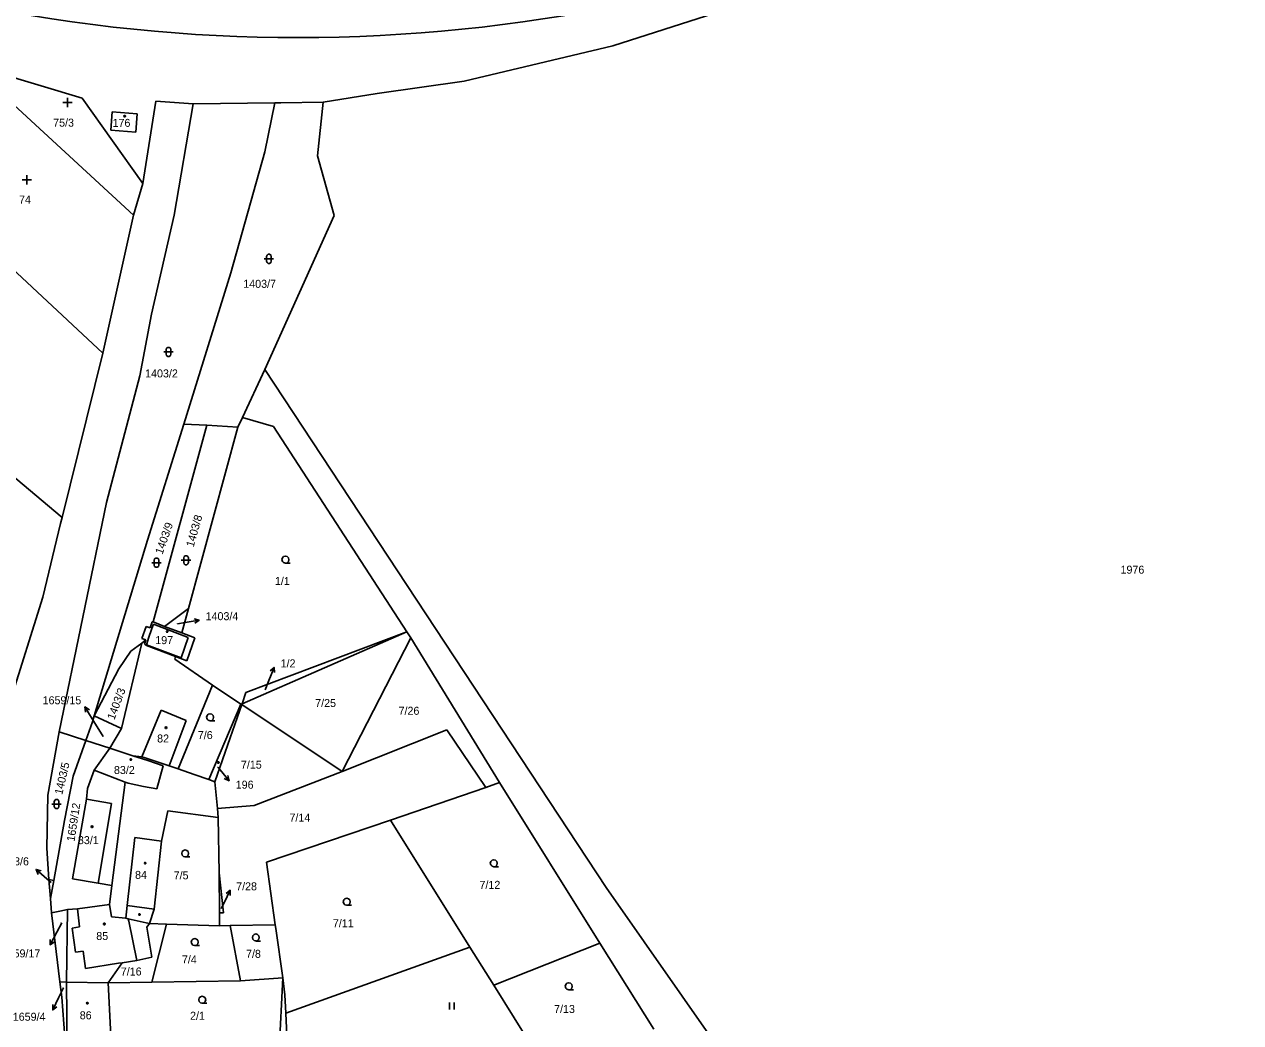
# Model space of a CAD drawing. Extents: x -802857 to -799647, y -1020285 to -1015884.
# Drawn here: x -801490 to -801231.6, y -1017461.1 to -1017248.9 of the extents above; entities that cross this region are included whole.
import ezdxf

# ---------------------------------------------------------------- set-up
doc = ezdxf.new("R2010")
doc.units = 0
for name, color, linetype in [('Default', 7, 'Continuous'), ('KN_HRANICE', 7, 'Continuous'), ('KN_KULTURY', 7, 'Continuous'), ('KN_PARCELY', 7, 'Continuous'), ('KN_SLUCKY', 7, 'Continuous'), ('Železniční svršek', 7, 'Continuous')]:
    doc.layers.add(name, color=color, linetype=linetype)

# ---------------------------------------------------------------- blocks, each defined once
blk = doc.blocks.new('304')
at = {"layer": 'Default'}
blk.add_lwpolyline([(0, 0), (-0.38, 0.1), (-0.65, 0.37), (-0.75, 0.74), (-0.65, 1.11), (-0.38, 1.38), (-0.01, 1.48), (0.36, 1.38), (0.63, 1.11), (0.73, 0.73), (0.63, 0.35), (0.36, 0.08), (-0.02, -0.02), (0.98, -0.02)], dxfattribs=at)
blk = doc.blocks.new('306')
at = {"layer": 'Default'}
for p, q in [((-0.5, 1.5), (-0.5, 0)), ((0.5, 0), (0.5, 1.5))]:
    blk.add_line(p, q, dxfattribs=at)
blk = doc.blocks.new('315')
at = {"layer": 'Default'}
for p, q in [((-1, 1), (1, 1)), ((0, 0), (0, 2))]:
    blk.add_line(p, q, dxfattribs=at)
blk = doc.blocks.new('316')
at = {"layer": 'Default'}
for points in [[(-1, 1), (0.27, 1), (1, 1)], [(-0.5, 1.5), (-0.4, 1.79), (-0.15, 1.97), (0.16, 1.97), (0.41, 1.79), (0.51, 1.5), (0.51, 0.5), (0.41, 0.21), (0.16, 0.03), (-0.15, 0.03), (-0.4, 0.21), (-0.5, 0.5), (-0.5, 1.5)]]:
    blk.add_lwpolyline(points, dxfattribs=at)
blk = doc.blocks.new('NAHRADNI_SYMBOL')
at = {"layer": 'Default'}
blk.add_lwpolyline([(0.09, 0.15), (0.18, 0), (0.09, -0.15), (-0.09, -0.15), (-0.18, 0), (-0.09, 0.15), (0.09, 0.15)], dxfattribs=at)
blk = doc.blocks.new('10292')
at = {"layer": 'Default'}
blk.add_line((0, 3), (0, 0), dxfattribs=at)
blk.add_lwpolyline([(-0.5, 2), (0, 3), (0.5, 2)], dxfattribs=at)
blk = doc.blocks.new('402')
at = {"layer": 'Default'}
blk.add_lwpolyline([(0.09, 0.15), (0.18, 0), (0.09, -0.15), (-0.09, -0.15), (-0.18, 0), (-0.09, 0.15), (0.09, 0.15)], dxfattribs=at)

msp = doc.modelspace()

# ---------------------------------------------------------------- linework, layer by layer
at = {"layer": 'KN_HRANICE'}
for p, q in [((-801619.51, -1017238.39), (-801481.95, -1017353.71)), ((-801318.92, -1017238.69), (-801364.93, -1017253.53)), ((-801364.93, -1017253.53), (-801396.54, -1017260.97)), ((-801477.73, -1017264.63), (-801501.56, -1017257.45)), ((-801466.82, -1017289.45), (-801501.56, -1017257.45)), ((-801396.54, -1017260.97), (-801415.01, -1017263.64)), ((-801415.01, -1017263.64), (-801426.49, -1017265.49)), ((-801477.73, -1017264.63), (-801464.79, -1017282.78)), ((-801464.79, -1017282.78), (-801462.07, -1017265.26)), ((-801454.13, -1017265.82), (-801462.07, -1017265.26)), ((-801454.13, -1017265.82), (-801458.15, -1017289.48)), ((-801454.13, -1017265.82), (-801436.73, -1017265.61)), ((-801438.87, -1017276.02), (-801436.73, -1017265.61)), ((-801436.73, -1017265.61), (-801435.52, -1017265.6)), ((-801435.52, -1017265.6), (-801426.49, -1017265.49)), ((-801426.49, -1017265.49), (-801427.72, -1017276.85)), ((-801471.6, -1017271.43), (-801471.3, -1017267.55)), ((-801471.3, -1017267.55), (-801466, -1017267.95)), ((-801466, -1017267.95), (-801466.29, -1017271.83)), ((-801466.29, -1017271.83), (-801471.6, -1017271.43)), ((-801473.28, -1017318.78), (-801518.94, -1017276.33)), ((-801446.14, -1017301.75), (-801438.87, -1017276.02)), ((-801427.72, -1017276.85), (-801424.14, -1017289.58)), ((-801466.82, -1017289.45), (-801464.79, -1017282.78)), ((-801473.28, -1017318.78), (-801466.82, -1017289.45)), ((-801458.15, -1017289.48), (-801462.97, -1017310.53)), ((-801424.14, -1017289.58), (-801438.92, -1017322.27)), ((-801456.12, -1017333.87), (-801446.14, -1017301.75)), ((-801462.97, -1017310.53), (-801465.45, -1017323.65)), ((-801481.95, -1017353.71), (-801473.28, -1017318.78)), ((-801465.45, -1017323.65), (-801472.56, -1017350.57)), ((-801443.65, -1017332.48), (-801438.92, -1017322.27)), ((-801438.92, -1017322.27), (-801366.39, -1017432.38)), ((-801463.78, -1017358.51), (-801456.12, -1017333.87)), ((-801451.19, -1017334.14), (-801462.64, -1017375.93)), ((-801451.19, -1017334.14), (-801456.12, -1017333.87)), ((-801444.59, -1017334.5), (-801451.19, -1017334.14)), ((-801444.59, -1017334.5), (-801443.65, -1017332.48)), ((-801443.65, -1017332.48), (-801437.03, -1017334.42)), ((-801455.08, -1017373.05), (-801444.59, -1017334.5)), ((-801437.03, -1017334.42), (-801408.69, -1017378.05)), ((-801472.56, -1017350.57), (-801482.61, -1017399.26)), ((-801486.04, -1017370.69), (-801482.28, -1017355.03)), ((-801482.28, -1017355.03), (-801481.95, -1017353.71)), ((-801475.12, -1017395.87), (-801463.78, -1017358.51)), ((-801493.03, -1017393.07), (-801486.04, -1017370.69)), ((-801460.21, -1017376.86), (-801455.08, -1017373.05)), ((-801456.5, -1017378.26), (-801455.08, -1017373.05)), ((-801464.99, -1017379.43), (-801464.11, -1017376.89)), ((-801464.11, -1017376.89), (-801463.26, -1017377.18)), ((-801463.26, -1017377.18), (-801462.81, -1017375.87)), ((-801462.81, -1017375.87), (-801462.64, -1017375.93)), ((-801462.64, -1017375.93), (-801460.21, -1017376.86)), ((-801460.21, -1017376.86), (-801456.5, -1017378.26)), ((-801453.76, -1017379.27), (-801456.5, -1017378.26)), ((-801443.73, -1017393.29), (-801408.69, -1017378.05)), ((-801442.91, -1017390.9), (-801408.69, -1017378.05)), ((-801407.88, -1017379.29), (-801408.69, -1017378.05)), ((-801469.37, -1017398.55), (-801465.04, -1017380.4)), ((-801465.04, -1017380.4), (-801467.33, -1017382.12)), ((-801464.14, -1017379.72), (-801465.04, -1017380.4)), ((-801464.14, -1017379.72), (-801464.99, -1017379.43)), ((-801464.45, -1017380.63), (-801464.14, -1017379.72)), ((-801464.01, -1017380.93), (-801464.45, -1017380.63)), ((-801453.76, -1017379.27), (-801455.47, -1017384.17)), ((-801422.42, -1017407.74), (-801407.88, -1017379.29)), ((-801407.88, -1017379.29), (-801389.06, -1017410.03)), ((-801469.88, -1017385.9), (-801467.33, -1017382.12)), ((-801457.88, -1017383.3), (-801464.01, -1017380.93)), ((-801457.88, -1017383.3), (-801458, -1017383.82)), ((-801455.47, -1017384.17), (-801457.88, -1017383.3)), ((-801475.12, -1017395.87), (-801469.88, -1017385.9)), ((-801450.03, -1017389.33), (-801458, -1017383.82)), ((-801450.03, -1017389.33), (-801457.32, -1017407.16)), ((-801443.97, -1017393.39), (-801450.03, -1017389.33)), ((-801443.73, -1017393.29), (-801442.91, -1017390.9)), ((-801443.97, -1017393.39), (-801450.79, -1017409.43)), ((-801446.23, -1017400.56), (-801443.8, -1017393.5)), ((-801443.97, -1017393.39), (-801443.73, -1017393.29)), ((-801443.8, -1017393.5), (-801443.73, -1017393.29)), ((-801443.8, -1017393.5), (-801422.42, -1017407.74)), ((-801475.51, -1017397.16), (-801475.12, -1017395.87)), ((-801469.37, -1017398.55), (-801475.12, -1017395.87)), ((-801476.91, -1017401.11), (-801475.51, -1017397.16)), ((-801471.82, -1017402.77), (-801469.37, -1017398.55)), ((-801400.24, -1017398.84), (-801422.42, -1017407.74)), ((-801391.91, -1017411.13), (-801400.24, -1017398.84)), ((-801484.97, -1017412.74), (-801482.61, -1017399.26)), ((-801476.91, -1017401.11), (-801482.61, -1017399.26)), ((-801479.6, -1017408.7), (-801476.91, -1017401.11)), ((-801471.82, -1017402.77), (-801476.91, -1017401.11)), ((-801449.49, -1017409.89), (-801446.23, -1017400.56)), ((-801475.18, -1017407.42), (-801471.82, -1017402.77)), ((-801471.82, -1017402.77), (-801466.9, -1017404.38)), ((-801466.9, -1017404.38), (-801463.71, -1017405.36)), ((-801466.9, -1017404.38), (-801464.99, -1017404.58)), ((-801464.3, -1017404.78), (-801464.99, -1017404.58)), ((-801459.24, -1017406.5), (-801464.3, -1017404.78)), ((-801463.71, -1017405.36), (-801460.5, -1017406.5)), ((-801460.5, -1017406.5), (-801461.81, -1017411.42)), ((-801457.32, -1017407.16), (-801459.24, -1017406.5)), ((-801481.43, -1017418.11), (-801479.6, -1017408.7)), ((-801475.18, -1017407.42), (-801476.57, -1017411.34)), ((-801468.57, -1017409.95), (-801475.18, -1017407.42)), ((-801453.89, -1017408.33), (-801457.32, -1017407.16)), ((-801450.79, -1017409.43), (-801453.89, -1017408.33)), ((-801422.42, -1017407.74), (-801441.13, -1017414.93)), ((-801476.57, -1017411.34), (-801476.78, -1017413.57)), ((-801468.57, -1017409.95), (-801471.37, -1017431.95)), ((-801467.94, -1017410.19), (-801468.57, -1017409.95)), ((-801464.69, -1017410.9), (-801467.94, -1017410.19)), ((-801461.81, -1017411.42), (-801464.69, -1017410.9)), ((-801449.49, -1017409.89), (-801450.79, -1017409.43)), ((-801449.49, -1017409.89), (-801448.95, -1017415.59)), ((-801412.18, -1017418.02), (-801391.91, -1017411.13)), ((-801391.91, -1017411.13), (-801389.06, -1017410.03)), ((-801367.72, -1017444.15), (-801389.06, -1017410.03)), ((-801485.18, -1017423.98), (-801484.97, -1017412.74)), ((-801476.78, -1017413.57), (-801479.73, -1017430.52)), ((-801459.51, -1017416.03), (-801460.82, -1017422.5)), ((-801448.78, -1017417.45), (-801459.51, -1017416.03)), ((-801441.13, -1017414.93), (-801448.95, -1017415.59)), ((-801448.95, -1017415.59), (-801448.78, -1017417.45)), ((-801483.75, -1017430.88), (-801481.43, -1017418.11)), ((-801448.78, -1017417.45), (-801448.56, -1017429.24)), ((-801438.55, -1017426.97), (-801412.18, -1017418.02)), ((-801395.3, -1017445.02), (-801412.18, -1017418.02)), ((-801484.77, -1017430.63), (-801485.18, -1017423.98)), ((-801460.82, -1017422.5), (-801462.42, -1017436.96)), ((-801438.55, -1017426.97), (-801436.67, -1017440.26)), ((-801448.56, -1017429.24), (-801447.64, -1017437.77)), ((-801448.56, -1017429.24), (-801448.55, -1017437.77)), ((-801484.44, -1017434.71), (-801484.77, -1017430.63)), ((-801484.77, -1017430.63), (-801483.75, -1017430.88)), ((-801484.44, -1017434.71), (-801483.75, -1017430.88)), ((-801479.73, -1017430.52), (-801474.31, -1017431.46)), ((-801474.31, -1017431.46), (-801471.37, -1017431.95)), ((-801471.37, -1017431.95), (-801471.88, -1017435.96)), ((-801366.39, -1017432.38), (-801324.28, -1017492.5)), ((-801484.2, -1017437.73), (-801484.44, -1017434.71)), ((-801482.44, -1017437.37), (-801484.2, -1017437.73)), ((-801484.2, -1017437.73), (-801482.44, -1017452.42)), ((-801480.79, -1017437.04), (-801482.44, -1017437.37)), ((-801481.05, -1017452.5), (-801480.79, -1017437.04)), ((-801480.79, -1017437.04), (-801478.66, -1017436.87)), ((-801478.66, -1017436.87), (-801471.88, -1017435.96)), ((-801471.88, -1017435.96), (-801471.48, -1017438.57)), ((-801462.42, -1017436.96), (-801463.38, -1017440.03)), ((-801471.48, -1017438.57), (-801468.43, -1017438.86)), ((-801467.91, -1017438.98), (-801468.43, -1017438.86)), ((-801464.08, -1017439.87), (-801467.91, -1017438.98)), ((-801463.38, -1017440.03), (-801464.08, -1017439.87)), ((-801463.93, -1017440.81), (-801463.38, -1017440.03)), ((-801463.38, -1017440.03), (-801459.78, -1017440.14)), ((-801462.91, -1017452.5), (-801459.78, -1017440.14)), ((-801459.78, -1017440.14), (-801448.54, -1017440.47)), ((-801447.64, -1017437.77), (-801448.55, -1017437.77)), ((-801448.55, -1017437.77), (-801448.54, -1017440.47)), ((-801436.67, -1017440.26), (-801446.24, -1017440.43)), ((-801436.67, -1017440.26), (-801436.56, -1017441.04)), ((-801462.92, -1017447.17), (-801463.93, -1017440.81)), ((-801446.24, -1017440.43), (-801448.54, -1017440.47)), ((-801446.24, -1017440.43), (-801444.06, -1017452.22)), ((-801436.56, -1017441.04), (-801435.08, -1017451.54)), ((-801395.3, -1017445.02), (-801434.42, -1017459.09)), ((-801390.25, -1017453.11), (-801395.3, -1017445.02)), ((-801367.72, -1017444.15), (-801390.25, -1017453.11)), ((-801356.25, -1017462.47), (-801367.72, -1017444.15)), ((-801469.2, -1017448.34), (-801466.08, -1017447.84)), ((-801466.08, -1017447.84), (-801462.92, -1017447.17)), ((-801469.2, -1017448.34), (-801472.2, -1017452.64)), ((-801482.44, -1017452.42), (-801481.05, -1017452.5)), ((-801482.44, -1017452.42), (-801481.99, -1017455.66)), ((-801472.2, -1017452.64), (-801481.05, -1017452.5)), ((-801481.05, -1017452.5), (-801480.85, -1017471.15)), ((-801462.91, -1017452.5), (-801472.2, -1017452.64)), ((-801472.2, -1017452.64), (-801471.55, -1017465.31)), ((-801444.06, -1017452.22), (-801462.91, -1017452.5)), ((-801435.08, -1017451.54), (-801444.06, -1017452.22)), ((-801435.08, -1017451.54), (-801436.26, -1017476.56)), ((-801435.08, -1017451.54), (-801434.61, -1017455.17)), ((-801379.24, -1017470.71), (-801390.25, -1017453.11)), ((-801480.85, -1017471.15), (-801481.99, -1017455.66)), ((-801434.61, -1017455.17), (-801434.42, -1017459.09)), ((-801434.42, -1017459.09), (-801433.35, -1017480.9))]:
    msp.add_line(p, q, dxfattribs=at)
at = {"layer": 'KN_PARCELY'}
for p, q in [((-801457.41, -1017376.35), (-801455.81, -1017376.07)), ((-801438.84, -1017390.35), (-801438.04, -1017388.36)), ((-801473.22, -1017400.28), (-801475.54, -1017396.53)), ((-801448.9, -1017406.77), (-801448.4, -1017407.37)), ((-801484.27, -1017431.32), (-801485.23, -1017430.49)), ((-801448.16, -1017436.83), (-801447.56, -1017435.64)), ((-801482.04, -1017439.87), (-801483.1, -1017441.87)), ((-801481.69, -1017453.66), (-801482.65, -1017455.66))]:
    msp.add_line(p, q, dxfattribs=at)
at = {"layer": 'KN_SLUCKY'}
for p, q in [((-801463.58, -1017379.36), (-801462.86, -1017377.32)), ((-801462.86, -1017377.32), (-801462.55, -1017376.41)), ((-801462.55, -1017376.41), (-801455.19, -1017379.23)), ((-801464.05, -1017380.77), (-801463.74, -1017379.86)), ((-801456.68, -1017383.56), (-801464.05, -1017380.77)), ((-801463.74, -1017379.86), (-801463.58, -1017379.36)), ((-801455.19, -1017379.23), (-801456.68, -1017383.56)), ((-801464.99, -1017404.58), (-801460.92, -1017394.66)), ((-801460.92, -1017394.66), (-801455.63, -1017396.89)), ((-801455.63, -1017396.89), (-801459.24, -1017406.5)), ((-801471.46, -1017414.5), (-801476.78, -1017413.57)), ((-801474.31, -1017431.46), (-801471.46, -1017414.5)), ((-801466.53, -1017421.73), (-801468.13, -1017436.19)), ((-801460.82, -1017422.5), (-801466.53, -1017421.73)), ((-801478.66, -1017436.87), (-801478.26, -1017440.73)), ((-801468.13, -1017436.19), (-801468.43, -1017438.86)), ((-801462.42, -1017436.96), (-801468.13, -1017436.19)), ((-801467.91, -1017438.98), (-801467.8, -1017439.52)), ((-801467.8, -1017439.52), (-801466.08, -1017447.84)), ((-801478.26, -1017440.73), (-801479.84, -1017440.98)), ((-801479.84, -1017440.98), (-801479.1, -1017446.07)), ((-801479.1, -1017446.07), (-801477.5, -1017445.91)), ((-801477.5, -1017445.91), (-801476.98, -1017449.6)), ((-801476.98, -1017449.6), (-801469.95, -1017448.47)), ((-801469.95, -1017448.47), (-801469.2, -1017448.34))]:
    msp.add_line(p, q, dxfattribs=at)
at = {"layer": 'Železniční svršek'}
msp.add_arc((-801431.93, -1016905.94), 345.8, 259.1164, 305.4132, dxfattribs=at)

# ---------------------------------------------------------------- block references
at = {"layer": 'KN_KULTURY'}
for name, p in [('315', (-801480.81, -1017266.56)), ('402', (-801468.66, -1017268.45)), ('315', (-801489.43, -1017282.97)), ('316', (-801438.02, -1017299.77)), ('316', (-801459.36, -1017319.54)), ('316', (-801461.92, -1017364.33)), ('316', (-801455.63, -1017363.81)), ('304', (-801434.51, -1017363.42)), ('402', (-801459.63, -1017377.97)), ('304', (-801450.51, -1017396.92)), ('402', (-801459.9, -1017398.39)), ('402', (-801467.35, -1017405.18)), ('NAHRADNI_SYMBOL', (-801448.77, -1017405.79)), ('316', (-801483.13, -1017415.62)), ('402', (-801475.59, -1017419.42)), ('304', (-801455.8, -1017425.84)), ('402', (-801464.3, -1017427.17)), ('304', (-801390.23, -1017427.94)), ('304', (-801421.48, -1017436.11)), ('402', (-801472.99, -1017440.12)), ('402', (-801465.5, -1017438.1)), ('304', (-801440.79, -1017443.71)), ('304', (-801453.78, -1017444.69)), ('304', (-801374.31, -1017454.09)), ('304', (-801452.18, -1017456.94)), ('NAHRADNI_SYMBOL', (-801476.59, -1017456.92)), ('306', (-801399.14, -1017458.26))]:
    msp.add_blockref(name, p, dxfattribs=at)
at = {"layer": 'KN_PARCELY'}
for p, rotation in [((-801455.81, -1017376.07), -80.05282100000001), ((-801438.04, -1017388.36), -21.897605), ((-801475.54, -1017396.53), 31.741862), ((-801448.4, -1017407.37), -139.81231900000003), ((-801485.23, -1017430.49), 49.15977900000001), ((-801447.56, -1017435.64), -26.595858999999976), ((-801483.1, -1017441.87), 152.005703), ((-801482.65, -1017455.66), 154.469422)]:
    msp.add_blockref('10292', p, dxfattribs=dict(at, rotation=rotation))

# ---------------------------------------------------------------- texts
for s, height, p in [('75/3', 1.7, (-801483.86, -1017270.67)), ('176', 1.7, (-801471.24, -1017270.72)), ('74', 1.7, (-801491.11, -1017287.01)), ('1403/7', 1.7, (-801443.47, -1017304.92)), ('1403/2', 1.7, (-801464.32, -1017323.96)), ('1976', 1.7, (-801257.08, -1017365.67)), ('1/1', 1.7, (-801436.75, -1017368.08)), ('1403/4', 1.7, (-801451.47, -1017375.55)), ('1403/4', 0.1, (-801457.71, -1017376.35)), ('197', 1.7, (-801462.17, -1017380.64)), ('1/2', 1.7, (-801435.53, -1017385.58)), ('1/2', 0.1, (-801438.99, -1017390.35)), ('1659/15', 1.7, (-801486.1, -1017393.42)), ('7/25', 1.7, (-801428.19, -1017394)), ('7/26', 1.7, (-801410.47, -1017395.65)), ('1659/15', 0.1, (-801473.57, -1017400.28)), ('82', 1.7, (-801461.77, -1017401.54)), ('7/6', 1.7, (-801453.12, -1017400.81)), ('83/2', 1.7, (-801470.94, -1017408.24)), ('196', 0.1, (-801449.05, -1017406.77)), ('7/15', 1.7, (-801443.97, -1017407.1)), ('196', 1.7, (-801445.07, -1017411.36)), ('7/14', 1.7, (-801433.65, -1017418.35)), ('83/1', 1.7, (-801478.6, -1017423.14)), ('1403/6', 1.7, (-801495.96, -1017427.64)), ('84', 1.7, (-801466.46, -1017430.53)), ('7/5', 1.7, (-801458.26, -1017430.62)), ('1403/6', 0.1, (-801484.57, -1017431.32)), ('7/28', 1.7, (-801444.98, -1017432.96)), ('7/12', 1.7, (-801393.28, -1017432.64)), ('7/28', 0.1, (-801448.36, -1017436.83)), ('1659/17', 0.1, (-801482.39, -1017439.87)), ('7/11', 1.7, (-801424.43, -1017440.81)), ('85', 1.7, (-801474.7, -1017443.51)), ('1659/17', 1.7, (-801494.8, -1017447.21)), ('7/4', 1.7, (-801456.5, -1017448.5)), ('7/8', 1.7, (-801442.88, -1017447.3)), ('7/16', 1.7, (-801469.49, -1017451.06)), ('1659/4', 0.1, (-801481.99, -1017453.66)), ('7/13', 1.7, (-801377.43, -1017459.02)), ('1659/4', 1.7, (-801492.44, -1017460.67)), ('86', 1.7, (-801478.21, -1017460.36)), ('2/1', 1.7, (-801454.77, -1017460.46))]:
    msp.add_text(s, height=height, dxfattribs=at).set_placement(p)
for s, rotation, p in [('1403/9', 70.703, (-801460.64, -1017361.7)), ('1403/8', 74.141, (-801454.03, -1017360.14)), ('1403/3', 69.614, (-801470.86, -1017396.86)), ('1403/5', 76.834, (-801481.93, -1017412.74)), ('1659/12', 81.245, (-801479.33, -1017422.67))]:
    msp.add_text(s, height=1.7, rotation=rotation, dxfattribs=at).set_placement(p)

doc.saveas('drawing.dxf')
